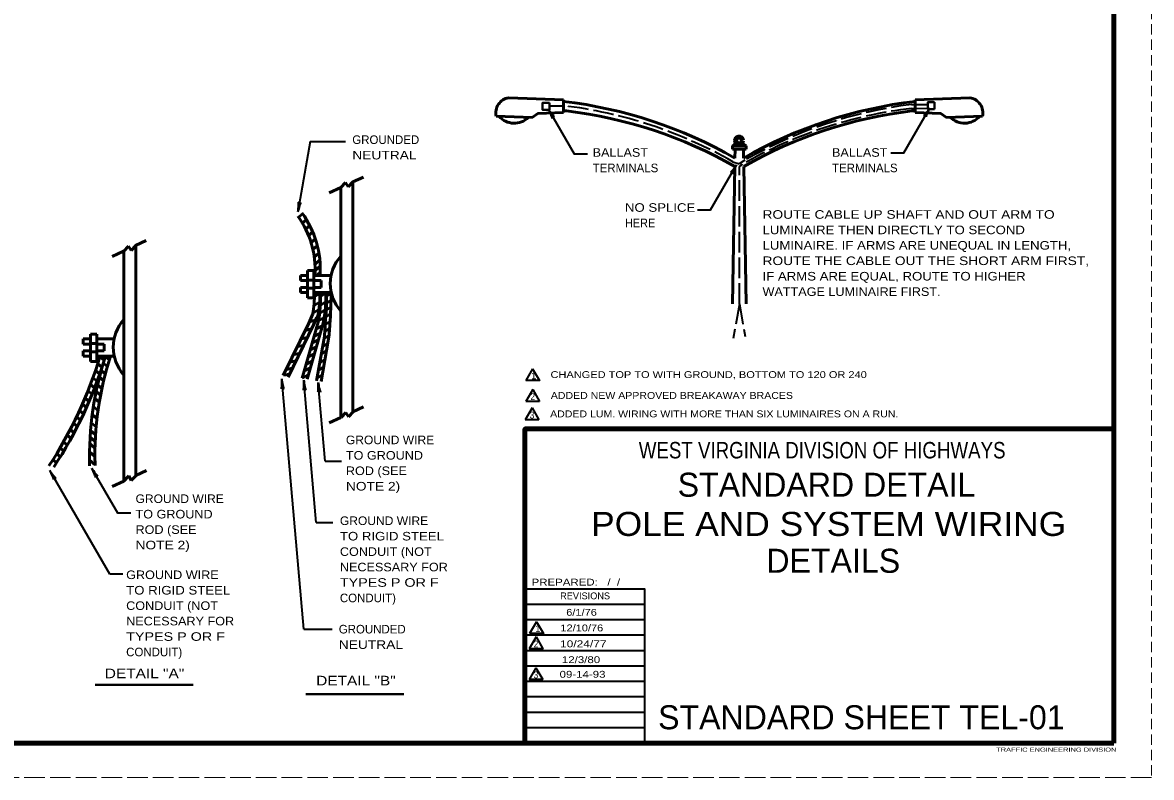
# Model space of a CAD drawing. Extents: x -153 to 527, y -247 to 194.
# Drawn here: x 197.9 to 527, y -246.5 to -26.5 of the extents above; entities that cross this region are included whole.
import ezdxf
from ezdxf.enums import TextEntityAlignment as Align

# ---------------------------------------------------------------- set-up
doc = ezdxf.new("R2010")
doc.units = 0
doc.header["$PDMODE"] = 32
doc.header["$PDSIZE"] = 0.5
doc.linetypes.add('LONG_DASHED', pattern=[7.5, 6, -1.5])
doc.linetypes.add('MEDIUM_DASHED', pattern=[4.5, 3, -1.5])
doc.layers.add('1', color=7, linetype='Continuous', lineweight=53)
doc.layers.add('61', color=7, linetype='Continuous', lineweight=35)

msp = doc.modelspace()

# ---------------------------------------------------------------- linework, layer by layer
at = {"layer": '1', "linetype": 'MEDIUM_DASHED', "lineweight": 13}
msp.add_line((526.958, 193.509), (526.938, -246.511), dxfattribs=at)
at = {"layer": '1'}
for p, q in [((355.608, -48.989), (339.618, -48.431)), ((355.608, -48.989), (355.608, -52.757)), ((458.067, -48.987), (474.057, -48.428)), ((458.067, -48.987), (458.067, -52.755)), ((356.515, -52.279), (355.608, -52.257)), ((457.16, -52.276), (458.067, -52.255)), ((346.422, -54.171), (335.928, -53.805)), ((467.253, -54.169), (477.747, -53.803)), ((404.832, -62.445), (406.053, -61.563)), ((404.832, -62.445), (408.832, -62.445)), ((404.832, -62.445), (404.832, -63.445)), ((408.832, -62.445), (407.542, -61.579)), ((408.832, -62.445), (408.832, -63.445)), ((404.832, -63.445), (408.832, -63.445)), ((405.608, -63.489), (405.567, -65.994)), ((408.067, -63.485), (408.109, -65.992)), ((405.525, -68.471), (404.858, -108.489)), ((408.15, -68.468), (408.817, -108.485)), ((294.16, -72.968), (297.257, -71.523)), ((287.288, -76.172), (290.658, -74.601)), ((290.714, -74.575), (292.078, -73.112)), ((290.714, -74.575), (290.714, -141.627)), ((292.078, -73.112), (292.85, -74.405)), ((292.85, -74.405), (294.214, -72.942)), ((294.214, -72.942), (294.214, -139.995)), ((279.58, -82.228), (278.382, -83.233)), ((280.689, -83.929), (279.485, -84.94)), ((281.651, -85.664), (280.434, -86.684)), ((281.272, -88.544), (281.238, -88.573)), ((282.523, -87.543), (281.286, -88.58)), ((227.439, -93.108), (228.803, -91.645)), ((228.803, -91.645), (229.575, -92.938)), ((229.575, -92.938), (230.939, -91.476)), ((230.885, -91.501), (233.982, -90.057)), ((230.939, -91.476), (230.939, -158.529)), ((282.004, -90.589), (283.269, -89.527)), ((283.855, -91.524), (282.552, -92.618)), ((283.202, -89.477), (283.241, -89.444)), ((224.013, -94.706), (227.383, -93.134)), ((227.439, -93.108), (227.439, -160.161)), ((284.321, -93.728), (282.964, -94.867)), ((284.585, -95.697), (283.167, -96.886)), ((284.704, -97.518), (283.218, -98.765)), ((278.892, -100.205), (278.892, -101.705)), ((278.892, -100.205), (280.975, -100.205)), ((278.892, -101.705), (281.008, -101.705)), ((281.008, -98.76), (282.808, -98.76)), ((281.008, -101.556), (282.808, -101.556)), ((282.805, -101.705), (285.008, -101.705)), ((282.808, -98.76), (282.808, -106.76)), ((282.822, -100.205), (287.892, -100.205)), ((284.706, -99.313), (283.643, -100.205)), ((285.008, -101.705), (285.008, -103.705)), ((278.892, -103.705), (278.892, -105.205)), ((278.892, -103.705), (281.008, -103.705)), ((278.892, -105.205), (280.975, -105.205)), ((281.008, -103.908), (282.808, -103.908)), ((282.789, -103.705), (285.008, -103.705)), ((282.822, -105.205), (287.892, -105.205)), ((283.049, -105.397), (283.049, -105.205)), ((281.008, -106.76), (282.808, -106.76)), ((284.558, -108.016), (282.848, -109.003)), ((284.551, -105.461), (283.025, -106.342)), ((286.3, -107.86), (284.755, -108.901)), ((286.272, -105.401), (284.803, -106.319)), ((287.927, -107.43), (286.539, -108.298)), ((287.932, -105.418), (286.566, -106.272)), ((284.334, -110.106), (282.595, -111.111)), ((286.158, -110.222), (284.534, -111.237)), ((287.692, -111.399), (286.328, -112.318)), ((287.836, -109.399), (286.416, -110.356)), ((281.339, -114.097), (273.887, -129.377)), ((282.758, -114.584), (275.306, -129.864)), ((284.083, -113.838), (279.397, -130.18)), ((285.549, -114.154), (280.863, -130.496)), ((283.312, -113.235), (281.507, -113.753)), ((285.34, -114.884), (283.53, -115.767)), ((285.869, -112.464), (284.165, -113.448)), ((287.541, -113.602), (286.166, -114.529)), ((217.733, -117.294), (219.533, -117.294)), ((219.533, -117.294), (219.533, -125.294)), ((280.967, -118.256), (279.12, -118.649)), ((282.178, -115.775), (280.292, -116.245)), ((284.735, -117.001), (282.925, -117.883)), ((287.232, -117.75), (285.779, -118.73)), ((287.419, -115.632), (286.043, -116.56)), ((215.617, -118.738), (215.617, -120.238)), ((215.617, -118.738), (217.7, -118.738)), ((215.617, -120.238), (217.733, -120.238)), ((217.733, -120.09), (219.533, -120.09)), ((219.53, -120.238), (221.733, -120.238)), ((219.547, -118.738), (224.617, -118.738)), ((221.733, -120.238), (221.733, -122.238)), ((279.815, -120.619), (278.003, -120.939)), ((283.569, -121.061), (281.759, -121.944)), ((284.171, -118.962), (282.361, -119.844)), ((285.72, -119.098), (283.631, -130.947)), ((287.013, -119.296), (284.919, -131.174)), ((286.894, -119.968), (285.388, -120.984)), ((215.617, -122.238), (215.617, -123.738)), ((215.617, -122.238), (217.733, -122.238)), ((215.617, -123.738), (217.7, -123.738)), ((217.733, -122.441), (219.533, -122.441)), ((219.513, -122.238), (221.733, -122.238)), ((219.547, -123.738), (224.617, -123.738)), ((220.468, -123.865), (221.736, -124.929)), ((222.065, -123.852), (223.255, -124.85)), ((278.681, -122.944), (276.869, -123.264)), ((282.984, -123.1), (281.174, -123.983)), ((286.064, -124.677), (284.557, -125.694)), ((286.516, -122.113), (285.017, -123.124)), ((217.733, -125.294), (219.533, -125.294)), ((219.186, -127.886), (220.389, -128.895)), ((219.825, -125.943), (221.075, -126.993)), ((220.831, -127.947), (222.064, -128.981)), ((221.429, -125.903), (221.421, -125.896)), ((221.459, -125.771), (222.671, -126.788)), ((276.567, -127.279), (274.755, -127.598)), ((277.625, -125.108), (275.778, -125.501)), ((281.846, -127.181), (280.036, -128.064)), ((282.383, -125.232), (280.573, -126.115)), ((285.673, -126.898), (284.166, -127.914)), ((218.442, -130.02), (219.66, -131.043)), ((220.324, -129.864), (221.578, -130.916)), ((275.76, -128.992), (273.948, -129.312)), ((281.208, -129.231), (279.397, -130.113)), ((285.269, -129.149), (283.762, -130.165)), ((216.987, -133.869), (218.177, -134.868)), ((217.71, -132.003), (218.915, -133.014)), ((219.368, -134.039), (220.668, -135.13)), ((219.787, -132.104), (221.064, -133.176)), ((215.367, -137.748), (216.531, -138.725)), ((216.141, -135.941), (217.317, -136.928)), ((218.976, -136.064), (220.3, -137.175)), ((213.659, -141.476), (214.799, -142.432)), ((214.528, -139.62), (215.68, -140.586)), ((218.237, -140.794), (219.623, -141.958)), ((218.568, -138.478), (219.923, -139.615)), ((290.77, -141.601), (292.134, -140.139)), ((292.134, -140.139), (292.906, -141.432)), ((292.906, -141.432), (294.27, -139.969)), ((294.216, -139.994), (297.313, -138.55)), ((212.758, -143.318), (213.886, -144.264)), ((217.961, -143.14), (219.381, -144.331)), ((287.344, -143.199), (290.714, -141.627)), ((210.958, -146.784), (212.065, -147.713)), ((211.841, -145.118), (212.958, -146.055)), ((217.617, -147.331), (219.101, -148.577)), ((217.751, -145.411), (219.205, -146.631)), ((208.88, -150.477), (209.966, -151.388)), ((209.874, -148.747), (210.97, -149.667)), ((217.522, -149.245), (219.038, -150.518)), ((206.794, -153.907), (207.862, -154.803)), ((207.871, -152.168), (208.949, -153.072)), ((217.456, -154.106), (219.074, -155.464)), ((217.458, -151.633), (219.017, -152.941)), ((219.055, -155.229), (219.085, -155.608)), ((230.941, -158.528), (234.038, -157.084)), ((224.069, -161.732), (227.439, -160.161)), ((227.495, -160.135), (228.859, -158.672)), ((228.859, -158.672), (229.631, -159.965)), ((229.631, -159.965), (230.995, -158.503))]:
    msp.add_line(p, q, dxfattribs=at)
at = {"layer": '1', "lineweight": 40}
for p, q in [((351.475, -49.926), (351.475, -51.926)), ((463.766, -49.725), (463.766, -51.725)), ((219.056, -219.586), (247.663, -219.586)), ((280.467, -222.277), (309.074, -222.277))]:
    msp.add_line(p, q, dxfattribs=at)
at = {"layer": '1', "linetype": 'LONG_DASHED', "lineweight": 40}
for p, q in [((355.461, -50.73), (351.475, -50.878)), ((407.777, -67.818), (406.858, -68.468))]:
    msp.add_line(p, q, dxfattribs=at)
at = {"layer": '1', "linetype": 'LONG_DASHED', "lineweight": 35}
for p, q in [((457.066, -50.365), (461.748, -50.346)), ((457.069, -51.532), (461.681, -51.417)), ((404.945, -67.079), (406.827, -67.648)), ((408.482, -66.643), (406.827, -67.648)), ((406.858, -108.489), (406.858, -68.468)), ((406.858, -108.489), (405.07, -118.633)), ((406.858, -108.489), (408.539, -118.021))]:
    msp.add_line(p, q, dxfattribs=at)
at = {"layer": '1', "lineweight": 35}
for p, q in [((281.8, -61.212), (278.192, -81.674)), ((281.8, -61.212), (292.072, -61.212)), ((346.582, -127.41), (344.582, -130.874)), ((279.877, -203.344), (273.493, -130.379)), ((283.537, -172.255), (279.909, -130.78)), ((286.125, -154.312), (284.119, -131.381)), ((346.631, -133.451), (344.631, -136.915)), ((346.631, -133.451), (348.631, -136.915)), ((348.631, -136.915), (344.631, -136.915)), ((346.429, -138.811), (344.429, -142.275)), ((346.429, -138.811), (348.429, -142.275)), ((348.429, -142.275), (344.429, -142.275)), ((286.125, -154.312), (290.92, -154.312)), ((223.32, -187.282), (205.865, -157.048)), ((283.537, -172.255), (288.322, -172.255)), ((227.118, -187.282), (223.32, -187.282)), ((379.338, -196.091), (344.358, -196.091)), ((379.338, -200.591), (344.358, -200.591)), ((279.877, -203.344), (288.15, -203.344)), ((347.724, -201.142), (345.724, -204.606)), ((379.338, -205.091), (344.358, -205.091)), ((347.608, -205.549), (345.608, -209.013)), ((379.338, -209.611), (344.358, -209.611)), ((379.338, -214.091), (344.358, -214.091)), ((347.565, -214.551), (345.565, -218.015)), ((347.565, -214.551), (349.565, -218.015)), ((379.338, -218.571), (344.358, -218.571)), ((349.565, -218.015), (345.565, -218.015)), ((379.338, -223.071), (344.358, -223.071)), ((379.338, -227.571), (344.358, -227.571)), ((379.338, -232.091), (344.358, -232.091))]:
    msp.add_line(p, q, dxfattribs=at)
at = {"layer": '1', "lineweight": 40}
for points in [[(351.475, -49.926), (349.475, -49.926), (349.475, -51.926), (351.475, -51.926)], [(463.766, -49.725), (461.766, -49.725), (461.766, -51.725), (463.766, -51.725)]]:
    msp.add_lwpolyline(points, dxfattribs=at)
at = {"layer": '1', "lineweight": 35}
for points in [[(362.562, -64.838), (358.764, -64.838), (351.202, -51.74)], [(451.02, -64.437), (454.818, -64.437), (462.38, -51.339)], [(394.68, -81.078), (398.479, -81.078), (406.041, -67.98)], [(346.582, -127.41), (348.582, -130.874), (344.582, -130.874)], [(229.455, -169.544), (225.657, -169.544), (218.095, -156.447)], [(379.338, -236.571), (379.338, -191.611), (344.358, -191.611)], [(347.724, -201.142), (349.724, -204.606), (345.724, -204.606)], [(347.608, -205.549), (349.608, -209.013), (345.608, -209.013)]]:
    msp.add_lwpolyline(points, dxfattribs=at)
at = {"layer": '1'}
for points in [[(355.608, -52.757), (348.113, -53.019), (346.422, -54.171)], [(458.067, -52.755), (465.563, -53.017), (467.253, -54.169)], [(405.033, -62.383), (408.563, -62.383), (405.1, -62.316), (408.429, -62.299), (405.234, -62.249), (408.345, -62.249), (405.334, -62.182), (408.262, -62.165), (405.434, -62.098), (408.128, -62.098), (405.535, -62.031), (408.027, -62.014), (405.652, -61.947), (407.91, -61.947), (408.63, -62.366), (407.492, -61.596), (408.63, -62.399), (407.475, -61.663), (407.676, -61.881), (407.375, -61.713), (407.626, -61.914), (407.308, -61.814), (407.409, -61.947), (407.258, -61.83), (407.174, -61.864), (407.091, -61.83), (407.392, -61.747), (407.074, -61.897), (407.693, -61.897), (407.04, -61.914), (407.726, -61.847), (407.459, -61.73), (407.81, -61.847), (407.76, -61.864), (405.602, -61.947), (404.999, -62.416), (406.003, -61.663), (405.853, -61.881), (406.07, -61.63), (405.936, -61.881)], [(405.936, -61.881), (406.137, -61.73), (406.07, -61.847), (406.17, -61.797), (406.221, -61.881), (406.338, -61.847), (406.405, -61.814), (406.388, -61.797), (406.304, -61.764), (406.221, -61.764), (406.204, -61.747), (406.204, -61.881), (406.037, -61.847), (405.919, -61.881), (405.802, -61.914), (405.869, -61.83), (405.802, -61.881)], [(405.802, -61.881), (406.07, -61.73), (406.17, -61.73), (406.237, -61.797), (406.338, -61.83), (406.354, -61.881), (406.187, -61.881), (406.07, -61.964), (406.806, -62.115), (407.191, -62.165), (406.388, -61.864)], [(281.008, -98.76), (281.008, -100.221), (281.008, -106.76)], [(217.733, -117.294), (217.733, -118.755), (217.733, -125.294)]]:
    msp.add_lwpolyline(points, dxfattribs=at)
at = {"layer": '1', "lineweight": 158}
msp.add_lwpolyline([(344.338, -236.531), (344.338, -144.951), (515.998, -144.951)], dxfattribs=at)
at = {"layer": '1', "lineweight": 90}
msp.add_circle((406.773, -60.877), 1, dxfattribs=at)
at = {"layer": '1'}
for centre, radius, start, end in [((340.355, -52.89), 4.52, 99.37905, 191.6795), ((473.321, -52.888), 4.52, 348.3205, 80.62095), ((340.105, -180.274), 131.701, 60.19516, 83.2397), ((341.306, -180.581), 129.201, 60.19516, 83.2397), ((473.57, -180.272), 131.701, 96.7603, 119.80484), ((472.369, -180.579), 129.201, 96.7603, 119.80484), ((341.22, -49.942), 5.9, 222.09121, 314.30098), ((472.456, -49.939), 5.9, 225.69902, 317.90879), ((256.563, -98.445), 28.156, 356.40839, 35.90092), ((256.563, -98.546), 26.656, 356.40839, 35.90092), ((299.591, -102.601), 11.967, 137.87912, 222.12088), ((263.354, -106.801), 21.239, 346.01908, 4.30944), ((252.458, -107.016), 32.352, 347.82744, 3.21036), ((252.458, -107.016), 33.852, 347.82752, 3.06797), ((183.516, -105.29), 103.052, 354.98062, 0.04745), ((183.315, -105.357), 104.552, 354.98066, 0.08358), ((238.281, -104.711), 44.773, 351.35006, 359.12221), ((216.099, -82.838), 72.343, 334.39874, 336.70651), ((236.316, -121.134), 11.967, 137.87912, 222.12088), ((301.132, -121.337), 19.575, 151.28461, 159.82064), ((251.316, -113.432), 34.867, 350.64855, 358.56325), ((252.609, -113.63), 34.867, 350.64855, 358.56325), ((103.531, -88.773), 122.089, 326.73645, 343.34848), ((103.707, -88.276), 123.589, 326.73645, 343.32557), ((311.522, -152.944), 94.073, 161.88261, 181.66408), ((311.589, -152.541), 92.573, 161.88261, 181.66408)]:
    msp.add_arc(centre, radius, start, end, dxfattribs=at)
at = {"layer": '1', "linetype": 'LONG_DASHED', "lineweight": 35}
for centre, radius, start, end in [((340.105, -180.274), 130.451, 60.19516, 83.2397), ((472.369, -180.579), 129.951, 96.76156, 119.80484), ((473.57, -180.272), 130.951, 97.24067, 119.80484)]:
    msp.add_arc(centre, radius, start, end, dxfattribs=at)
at = {"layer": '1', "lineweight": 40}
for centre, major_axis, ratio, start_param, end_param in [((351.579, -52.816), (-0.726, 1.609), 0.07063, 3.1407148, 5.41811), ((351.987, -52.547), (-1.028, 1.468), 0.122415, 0.8963533, 3.1415927), ((461.595, -52.146), (1.028, 1.468), 0.122415, 3.1415927, 5.386832), ((462.003, -52.415), (0.726, 1.609), 0.07063, 0.8650754, 3.1424706), ((405.256, -68.787), (1.028, 1.468), 0.122415, 3.1415927, 5.386832), ((405.664, -69.057), (0.726, 1.609), 0.07063, 0.8650754, 3.1424706), ((278.109, -80.551), (-0.156, -1.786), 0.122415, 0.8963533, 3.1415927), ((278.595, -80.607), (0.478, 1.699), 0.07063, 6.2823074, 8.5597026), ((273.38, -131.514), (-0.022, -1.765), 0.07063, 6.2823074, 8.5597026), ((273.863, -131.442), (-0.311, 1.765), 0.122415, 0.8963533, 3.1415927), ((279.796, -131.915), (-0.022, -1.765), 0.07063, 6.2823074, 8.5597026), ((280.279, -131.843), (-0.311, 1.765), 0.122415, 0.8963533, 3.1415927), ((284.006, -132.516), (-0.022, -1.765), 0.07063, 6.2823074, 8.5597026), ((284.49, -132.445), (-0.311, 1.765), 0.122415, 0.8963533, 3.1415927), ((206.242, -158.125), (-0.726, 1.609), 0.07063, 3.1407148, 5.41811), ((206.65, -157.855), (-1.028, 1.468), 0.122415, 0.8963533, 3.1415927), ((218.472, -157.523), (-0.726, 1.609), 0.07063, 3.1407148, 5.41811), ((218.88, -157.254), (-1.028, 1.468), 0.122415, 0.8963533, 3.1415927)]:
    msp.add_ellipse(centre, major_axis=major_axis, ratio=ratio, start_param=start_param, end_param=end_param, dxfattribs=at)
at = {"layer": '1'}
msp.add_point((405.802, -61.881), dxfattribs=at)
at = {"layer": '61', "lineweight": 158}
for p, q in [((515.978, 183.509), (515.998, -236.531)), ((515.998, -236.531), (-123.062, -236.511))]:
    msp.add_line(p, q, dxfattribs=at)
at = {"layer": '61', "linetype": 'LONG_DASHED', "lineweight": 13}
msp.add_line((526.938, -246.511), (-153.122, -246.531), dxfattribs=at)

# ---------------------------------------------------------------- texts
at = {"layer": '1'}
for s, height, p in [('GROUNDED', 2.5, (294.037, -61.898)), ('TERMINALS', 2.5, (364.085, -70.125)), ('TERMINALS', 2.5, (433.858, -70.125)), ('1', 2, (346.178, -130.449)), ('CONDUIT)', 2.5, (290.419, -195.464)), ('REVISIONS', 1.998, (354.618, -194.611)), ('GROUNDED', 2.5, (290.101, -204.569)), ('1', 2, (347.353, -204.159)), ('CONDUIT)', 2.5, (228.126, -211.216)), ('STANDARD SHEET TEL-01', 6.993, (383.178, -232.491))]:
    msp.add_text(s, height=height, dxfattribs=at).set_placement(p)
for s, height, width, p in [('NEUTRAL  ', 2.5, 1.2, (294.037, -66.398)), ('BALLAST', 2.5, 1.1, (364.085, -65.625)), ('BALLAST', 2.5, 1.1, (433.858, -65.625)), ('NO SPLICE', 2.5, 1.15, (373.509, -81.665)), ('ROUTE CABLE UP SHAFT AND OUT ARM TO', 2.5, 1.2, (413.608, -83.692)), ('HERE', 2.5, 0.95, (373.509, -86.165)), ('LUMINAIRE THEN DIRECTLY TO SECOND', 2.5, 1.15, (413.608, -88.192)), ('LUMINAIRE. IF ARMS ARE UNEQUAL IN LENGTH,', 2.5, 1.15, (413.608, -92.692)), ('ROUTE THE CABLE OUT THE SHORT ARM FIRST,', 2.5, 1.2, (413.608, -97.192)), ('IF ARMS ARE EQUAL, ROUTE TO HIGHER', 2.5, 1.15, (413.608, -101.692)), ('WATTAGE LUMINAIRE FIRST.', 2.5, 1.1, (413.608, -106.192)), ('CHANGED TOP TO WITH GROUND, BOTTOM TO 120 OR 240', 2, 1.2, (351.811, -130.117)), ('2', 2, 0.9, (345.961, -136.556)), ('ADDED NEW APPROVED BREAKAWAY BRACES', 2, 1.15, (351.9, -136.205)), ('3', 2, 0.9, (345.759, -141.916)), ('ADDED LUM. WIRING WITH MORE THAN SIX LUMINAIRES ON A RUN.', 2, 1.15, (351.698, -141.566)), ('GROUND WIRE', 2.5, 1.05, (292.173, -149.403)), ('TO GROUND', 2.5, 1.1, (292.173, -153.903)), ('ROD (SEE', 2.5, 1.1, (292.173, -158.403)), ('NOTE 2)', 2.5, 1.2, (292.173, -162.903)), ('GROUND WIRE', 2.5, 1.05, (230.857, -166.546)), ('TO GROUND', 2.5, 1.1, (230.857, -171.046)), ('GROUND WIRE', 2.5, 1.05, (290.419, -172.964)), ('ROD (SEE', 2.5, 1.1, (230.857, -175.546)), ('NOTE 2)', 2.5, 1.2, (230.857, -180.046)), ('TO RIGID STEEL', 2.5, 1.15, (290.419, -177.464)), ('CONDUIT (NOT', 2.5, 1.1, (290.419, -181.964)), ('NECESSARY FOR', 2.5, 1.1, (290.419, -186.464)), ('GROUND WIRE ', 2.5, 1.1, (228.126, -188.716)), ('TO RIGID STEEL', 2.5, 1.15, (228.126, -193.216)), ('TYPES P OR F', 2.5, 1.25, (290.419, -190.964)), ('PREPARED:   /  /  ', 1.998, 1.25, (346.298, -190.611)), ('CONDUIT (NOT', 2.5, 1.1, (228.126, -197.716)), ('6/1/76', 2, 1.2, (356.395, -199.412)), ('NECESSARY FOR', 2.5, 1.1, (228.126, -202.216)), ('12/10/76', 2, 1.2, (354.687, -203.959)), ('TYPES P OR F', 2.5, 1.25, (228.126, -206.716)), ('NEUTRAL  ', 2.5, 1.2, (290.101, -209.069)), ('2', 2, 0.9, (346.917, -208.64)), ('10/24/77', 2, 1.3, (354.597, -208.593)), ('12/3/80', 2, 1.25, (355.129, -213.209)), ('3', 2, 0.9, (346.895, -217.656)), ('TRAFFIC ENGINEERING DIVISION', 1.2, 1.35, (481.718, -239.031))]:
    msp.add_text(s, height=height, dxfattribs=dict(at, width=width)).set_placement(p)
for s, height, width, p in [('WEST VIRGINIA DIVISION OF HIGHWAYS', 4.795, 0.85, (430.986, -153.551)), ('POLE AND SYSTEM WIRING', 7, 1.1, (432.883, -176.143)), ('DETAIL "A"', 2.8, 1.2, (233.481, -217.618)), ('DETAIL "B"', 2.8, 1.2, (295.093, -219.707)), ('09-14-93', 2, 1.25, (361.147, -217.471))]:
    msp.add_text(s, height=height, dxfattribs=dict(at, width=width)).set_placement(p, align=Align.CENTER)
for s, height, p in [('STANDARD DETAIL', 6.993, (432.255, -164.711)), ('DETAILS', 7, (434.222, -186.881))]:
    msp.add_text(s, height=height, dxfattribs=at).set_placement(p, align=Align.CENTER)

doc.saveas('drawing.dxf')
